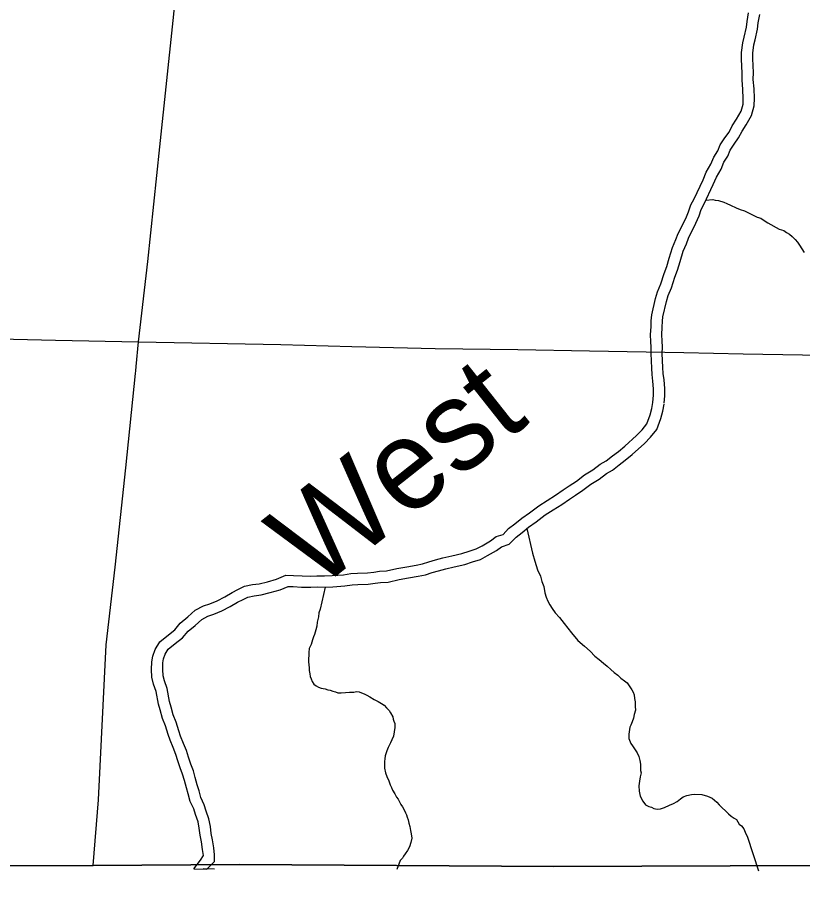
# Model space of a CAD drawing. Extents: x 2010165 to 2382125, y 1060529 to 1407316.
# Drawn here: x 2131582 to 2135077, y 1221171 to 1225012 of the extents above; entities that cross this region are included whole.
import ezdxf

# ---------------------------------------------------------------- set-up
doc = ezdxf.new("R2010")
doc.units = 0
for name, color, linetype in [('GM_X_Adjacent_County', 7, 'Continuous'), ('GM_X_City_Street', 7, 'Continuous'), ('GM_X_Corporation', 7, 'Continuous'), ('GM_X_County', 7, 'Continuous'), ('GM_X_Interstate_Route', 7, 'Continuous'), ('GM_X_Major_River', 7, 'Continuous'), ('GM_X_Major_River_Text', 7, 'Continuous'), ('GM_X_Minor_River', 7, 'Continuous'), ('GM_X_State_Route', 7, 'Continuous'), ('GM_X_Township', 7, 'Continuous')]:
    doc.layers.add(name, color=color, linetype=linetype)

msp = doc.modelspace()

# ---------------------------------------------------------------- linework, layer by layer
at = {"layer": 'GM_X_Adjacent_County'}
msp.add_lwpolyline([(2126567.4, 1221231.3), (2131919.6, 1221238.9), (2132570.2, 1221243.7), (2133969.3, 1221233.9), (2135145.8, 1221238.6), (2135226.5, 1221239.7), (2135440.8, 1221237.8), (2135741.4, 1221239.3), (2136043.5, 1221235.6), (2136342.6, 1221236.4), (2136645.5, 1221239.3), (2136937.2, 1221238.6), (2139646.1, 1221239.5), (2139604.7, 1218402.7)], dxfattribs=at)
at = {"layer": 'GM_X_City_Street'}
for points in [[(2126558, 1221231.4), (2126567.4, 1221231.3), (2131919.6, 1221238.9)], [(2132570.1, 1221243.7), (2133969.3, 1221233.9), (2135145.8, 1221238.6), (2135226.5, 1221239.7), (2135440.8, 1221237.8), (2135741.4, 1221239.3), (2136043.5, 1221235.6), (2136342.6, 1221236.4), (2136645.5, 1221239.3), (2136937.2, 1221238.6), (2139646.1, 1221239.5)]]:
    msp.add_lwpolyline(points, dxfattribs=at)
at = {"layer": 'GM_X_Corporation'}
msp.add_lwpolyline([(2135145.8, 1221238.6), (2133969.3, 1221233.9), (2132570.2, 1221243.7), (2131919.6, 1221238.9), (2126567.4, 1221231.3)], dxfattribs=at)
at = {"layer": 'GM_X_County'}
msp.add_lwpolyline([(2139604.7, 1218402.7), (2139646.1, 1221239.5), (2136937.2, 1221238.6), (2136645.5, 1221239.3), (2136342.6, 1221236.4), (2136043.5, 1221235.6), (2135741.4, 1221239.3), (2135440.8, 1221237.8), (2135226.5, 1221239.7), (2135145.8, 1221238.6), (2133969.3, 1221233.9), (2132570.2, 1221243.7), (2131919.6, 1221238.9), (2126567.4, 1221231.3)], dxfattribs=at)
at = {"layer": 'GM_X_Interstate_Route'}
for points in [[(2129183.2, 1224428.9), (2129406.8, 1224274.3), (2129545.2, 1224186), (2129820.4, 1224036.4), (2130010.5, 1223946.5), (2130302.5, 1223828.1), (2130555.7, 1223745.8), (2130707.1, 1223706.7), (2130861.1, 1223671.3), (2131070.1, 1223632.6), (2131226.9, 1223608.1), (2131383.5, 1223594.5), (2131565, 1223580), (2131751.7, 1223575), (2132122, 1223568.4)], [(2132122, 1223568.4), (2132754.5, 1223556.1), (2133070.4, 1223547.3), (2133441.3, 1223538.9), (2133809.4, 1223534), (2134128.1, 1223528.8), (2134548.5, 1223520.7), (2134812.2, 1223515.2), (2135075.9, 1223509.7), (2135241.7, 1223508.5), (2135762.8, 1223496), (2136026.5, 1223486.9), (2136287.6, 1223474.1), (2136551.4, 1223454), (2137128.7, 1223392.3), (2137651.1, 1223312), (2138066.5, 1223227.3), (2138270.1, 1223181.3), (2138476.5, 1223131.7), (2138680.1, 1223074.8), (2138977.2, 1222989.7), (2139610, 1222769.1), (2139632.9, 1222759.9)]]:
    msp.add_lwpolyline(points, dxfattribs=at)
at = {"layer": 'GM_X_Major_River'}
for p, q in [((2132367, 1221223.4), (2132424.7, 1221222.9)), ((2132459.4, 1221223.2), (2132409.4, 1221223.4))]:
    msp.add_line(p, q, dxfattribs=at)
for points in [[(2134410.4, 1223298.9), (2134413, 1223331), (2134413.4, 1223359.1), (2134410, 1223393.2), (2134406.5, 1223423.4), (2134405, 1223451.5), (2134402.1, 1223515.7), (2134402.5, 1223543.8), (2134401, 1223569.9), (2134399.5, 1223600), (2134402.1, 1223636.1), (2134402.5, 1223662.2), (2134404.9, 1223688.2), (2134422.2, 1223760.2), (2134430.7, 1223790.1), (2134445.3, 1223826), (2134460.1, 1223871.9), (2134472.6, 1223903.8), (2134483.3, 1223939.8), (2134498.1, 1223987.7), (2134512.7, 1224023.6), (2134523.2, 1224049.5), (2134556.3, 1224117.2), (2134568.9, 1224147.1), (2134579.4, 1224177.1), (2134593.9, 1224204.9), (2134633.3, 1224288.6), (2134647.9, 1224322.4), (2134668.5, 1224358.2), (2134681.1, 1224390.1), (2134699.6, 1224417.9), (2134710, 1224443.8), (2134730.6, 1224475.6), (2134749, 1224501.4), (2134763.5, 1224529.3), (2134782, 1224559.1), (2134802.7, 1224594.9), (2134811.2, 1224624.8), (2134811.6, 1224650.9), (2134810.3, 1224691.1), (2134807, 1224733.2), (2134807.5, 1224765.3), (2134806, 1224793.4), (2134804.6, 1224827.6), (2134805, 1224855.7), (2134809.8, 1224897.7), (2134816.2, 1224923.7), (2134827, 1224967.7), (2134829.4, 1224993.7), (2134836, 1225031.7)], [(2134460.3, 1223294.9), (2134463, 1223328.6), (2134463.5, 1223361.1), (2134459.7, 1223398.6), (2134456.4, 1223427.6), (2134454.9, 1223454), (2134452.1, 1223516.4), (2134452.6, 1223544.9), (2134450.9, 1223572.6), (2134449.6, 1223599.5), (2134452.1, 1223633.9), (2134452.5, 1223659.4), (2134454.4, 1223680), (2134470.6, 1223747.5), (2134478.1, 1223773.8), (2134492.3, 1223808.9), (2134507.2, 1223855.1), (2134520, 1223887.6), (2134531.2, 1223925.3), (2134545.2, 1223970.8), (2134559.1, 1224004.8), (2134568.9, 1224029.1), (2134601.9, 1224096.5), (2134615.6, 1224129.1), (2134625.4, 1224157.1), (2134638.7, 1224182.7), (2134678.9, 1224268), (2134692.7, 1224300), (2134713.7, 1224336.5), (2134725.7, 1224366.8), (2134744.1, 1224394.5), (2134754.6, 1224420.7), (2134771.9, 1224447.5), (2134791.8, 1224475.2), (2134807, 1224504.5), (2134825, 1224533.4), (2134849.1, 1224575.2), (2134861.1, 1224617.5), (2134861.7, 1224651.3), (2134860.3, 1224693.8), (2134857, 1224734.8), (2134857.6, 1224766.3), (2134856, 1224795.8), (2134854.6, 1224828.2), (2134855, 1224852.5), (2134859.1, 1224888.9), (2134864.8, 1224911.8), (2134876.4, 1224959.4), (2134879, 1224987.1), (2134885.4, 1225023.9)], [(2132367, 1221223.4), (2132398, 1221262.1), (2132410, 1221283.9), (2132406.4, 1221310), (2132401, 1221344.2), (2132395.5, 1221374.4), (2132392, 1221404.5), (2132386.4, 1221432.7), (2132375, 1221465), (2132367.4, 1221491.2), (2132351.9, 1221523.6), (2132342.5, 1221557.8), (2132334.9, 1221584), (2132325.4, 1221616.2), (2132317.9, 1221644.5), (2132306.3, 1221672.7), (2132296.9, 1221705), (2132287.3, 1221733.2), (2132275.8, 1221763.5), (2132262.3, 1221795.8), (2132252.8, 1221822.1), (2132241.4, 1221860.3), (2132227.9, 1221892.7), (2132218.5, 1221930.9), (2132211, 1221957.1), (2132199.9, 1222013.5), (2132188.4, 1222045.8), (2132180.9, 1222076), (2132179.5, 1222110.1), (2132180.1, 1222144.2), (2132184.5, 1222170.2), (2132195, 1222200.2), (2132215.6, 1222233.9), (2132254.2, 1222265.4), (2132282.6, 1222287.1), (2132307.1, 1222316.8), (2132341.6, 1222344.3), (2132374.2, 1222373.9), (2132410.6, 1222393.4), (2132438.8, 1222403), (2132471, 1222416.5), (2132505.4, 1222434), (2132537.7, 1222453.6), (2132564, 1222467.2), (2132592.3, 1222480.8), (2132628.4, 1222488.3), (2132658.5, 1222491.8), (2132694.7, 1222501.3), (2132735, 1222512.7), (2132777.3, 1222530.1), (2132811.4, 1222529.5), (2132849.4, 1222526.9), (2132887.4, 1222526.3), (2132915.5, 1222527.9), (2132949.5, 1222527.4), (2132983.6, 1222528.8), (2133033.7, 1222532.1), (2133065.9, 1222537.6), (2133095.9, 1222539.1), (2133140, 1222540.4), (2133168.1, 1222544), (2133194.2, 1222547.6), (2133224.3, 1222549.1), (2133270.5, 1222560.4), (2133314.7, 1222567.8), (2133356.9, 1222575.1), (2133385, 1222580.7), (2133413.2, 1222590.3), (2133443.4, 1222597.8), (2133475.6, 1222607.4), (2133515.8, 1222616.8), (2133560, 1222626.1), (2133592.2, 1222637.6), (2133624.4, 1222647.2), (2133650.7, 1222660.8), (2133687.1, 1222682.3), (2133713.5, 1222701.9), (2133743.7, 1222711.5), (2133768.2, 1222737.2), (2133796.5, 1222758.8), (2133827, 1222784.4), (2133861.5, 1222807.9), (2133902, 1222839.4), (2133940.5, 1222862.9), (2133976.9, 1222886.4), (2134011.4, 1222909.9), (2134037.7, 1222927.6), (2134070.1, 1222949.1), (2134106.6, 1222976.6), (2134143, 1222998.1), (2134175.5, 1223023.7), (2134201.8, 1223039.3), (2134230.2, 1223061), (2134256.6, 1223080.6), (2134285, 1223104.3), (2134337.9, 1223151.6), (2134362.3, 1223177.3), (2134382.8, 1223203), (2134397.5, 1223242.9), (2134405.9, 1223270.9), (2134410.4, 1223298.9)], [(2132424.7, 1221222.9), (2132459.6, 1221257.3), (2132460.1, 1221286.9), (2132455.9, 1221317.3), (2132450.3, 1221352.6), (2132445, 1221381.8), (2132441.4, 1221412.2), (2132434.8, 1221446), (2132422.6, 1221480.3), (2132414.3, 1221509.1), (2132399, 1221541.1), (2132390.6, 1221571.4), (2132382.9, 1221598), (2132373.6, 1221629.8), (2132365.4, 1221660.4), (2132353.6, 1221689.3), (2132344.6, 1221720), (2132334.4, 1221750.1), (2132322.3, 1221782), (2132309, 1221814), (2132300.3, 1221837.8), (2132288.6, 1221877.1), (2132275.6, 1221908.3), (2132266.9, 1221943.8), (2132259.6, 1221968.9), (2132248.3, 1222026.8), (2132236.4, 1222060.2), (2132230.7, 1222083.1), (2132229.5, 1222110.7), (2132230, 1222139.6), (2132233.1, 1222157.6), (2132240.5, 1222178.6), (2132253.9, 1222200.6), (2132285.2, 1222226.1), (2132317.5, 1222250.8), (2132342.4, 1222280.9), (2132374.1, 1222306.2), (2132403.3, 1222332.7), (2132430.6, 1222347.3), (2132456.5, 1222356.2), (2132492.1, 1222371.1), (2132529.7, 1222390.3), (2132562.2, 1222409.9), (2132586.4, 1222422.5), (2132608.4, 1222433.1), (2132636.4, 1222438.8), (2132667.8, 1222442.5), (2132707.9, 1222453), (2132751.4, 1222465.3), (2132786.8, 1222479.9), (2132809.3, 1222479.5), (2132847.3, 1222476.9), (2132888.4, 1222476.3), (2132916.5, 1222477.8), (2132950.2, 1222477.3), (2132986.3, 1222478.9), (2133039.6, 1222482.3), (2133071.4, 1222487.8), (2133097.9, 1222489.1), (2133143.9, 1222490.5), (2133174.7, 1222494.4), (2133198.9, 1222497.7), (2133231.6, 1222499.4), (2133280.6, 1222511.4), (2133323.1, 1222518.4), (2133366, 1222525.9), (2133398, 1222532.3), (2133427.4, 1222542.3), (2133456.6, 1222549.6), (2133488.4, 1222559), (2133526.7, 1222567.9), (2133573.7, 1222577.8), (2133607.8, 1222590.1), (2133643.2, 1222600.6), (2133675, 1222617), (2133714.9, 1222640.6), (2133736.6, 1222656.8), (2133771, 1222667.7), (2133801.6, 1222699.8), (2133827.8, 1222719.7), (2133857.3, 1222744.5), (2133890.9, 1222767.5), (2133930.5, 1222798.2), (2133967.1, 1222820.5), (2134004.6, 1222844.7), (2134039.4, 1222868.5), (2134065.5, 1222886), (2134099, 1222908.3), (2134134.5, 1222935), (2134171.4, 1222956.8), (2134203.9, 1222982.4), (2134229.8, 1222997.8), (2134260.3, 1223021), (2134287.5, 1223041.3), (2134317.7, 1223066.4), (2134372.7, 1223115.6), (2134400.1, 1223144.4), (2134427, 1223178.2), (2134444.9, 1223227), (2134454.8, 1223259.6), (2134459.8, 1223291)]]:
    msp.add_lwpolyline(points, dxfattribs=at)
at = {"layer": 'GM_X_Minor_River'}
for points in [[(2134646.3, 1224198.8), (2134677.3, 1224200.8), (2134687.4, 1224198.9), (2134701.4, 1224197.1), (2134725.6, 1224189.4), (2134739.7, 1224183.6), (2134755.9, 1224175.8), (2134780.1, 1224164.1), (2134798.3, 1224156.4), (2134818.4, 1224150.7), (2134838.6, 1224140.9), (2134856.8, 1224131.1), (2134874.9, 1224123.4), (2134891.1, 1224117.6), (2134905.2, 1224107.8), (2134921.4, 1224098), (2134972, 1224068.6), (2134992.1, 1224062.9), (2135004.3, 1224055), (2135018.4, 1224047.2), (2135030.6, 1224037.4), (2135042.8, 1224023.5), (2135053, 1224011.6), (2135063.2, 1223997.7), (2135073.5, 1223981.8), (2135083.8, 1223965.9)], [(2133850, 1222738.3), (2133874, 1222627.8), (2133884.5, 1222591.9), (2133897.1, 1222553.9), (2133909.5, 1222526), (2133915.9, 1222502), (2133924.3, 1222480.1), (2133928.7, 1222452), (2133935, 1222432.1), (2133943.3, 1222414.1), (2133951.5, 1222398.2), (2133961.8, 1222382.3), (2133976.1, 1222362.4), (2133994.4, 1222342.6), (2134014.9, 1222314.8), (2134047.6, 1222273.2), (2134076.1, 1222239.5), (2134106.6, 1222213.8), (2134131, 1222192.1), (2134151.3, 1222170.3), (2134171.6, 1222154.6), (2134189.9, 1222138.8), (2134206.1, 1222125), (2134222.4, 1222111.1), (2134238.6, 1222097.3), (2134254.8, 1222085.5), (2134267.1, 1222071.7), (2134283.3, 1222059.9), (2134295.4, 1222052), (2134307.7, 1222034.1), (2134315.9, 1222020.2), (2134322.1, 1222010.3), (2134326.3, 1221998.3), (2134328.5, 1221982.3), (2134330.8, 1221966.2), (2134331, 1221946.2), (2134333.3, 1221930.1), (2134327.6, 1221910), (2134323.8, 1221893.9), (2134318, 1221877.8), (2134312.2, 1221863.6), (2134308.3, 1221853.5), (2134302.8, 1221823.3), (2134303, 1221803.3), (2134311.4, 1221781.3), (2134319.5, 1221771.4), (2134331.8, 1221753.5), (2134340.1, 1221739.6), (2134348.3, 1221723.7), (2134352.6, 1221705.7), (2134354.8, 1221689.7), (2134355, 1221675.6), (2134355.2, 1221661.6), (2134357.4, 1221651.6), (2134353.6, 1221633.4), (2134349.9, 1221613.3), (2134348.2, 1221593.2), (2134348.5, 1221569.2), (2134352.9, 1221547.1), (2134365.2, 1221525.3), (2134377.5, 1221509.4), (2134391.6, 1221501.6), (2134403.7, 1221497.7), (2134413.8, 1221491.8), (2134429.9, 1221490.1), (2134443.9, 1221490.3), (2134461.9, 1221496.6), (2134483.8, 1221506.9), (2134501.7, 1221515.2), (2134517.6, 1221523.5), (2134533.5, 1221535.7), (2134545.4, 1221543.9), (2134561.4, 1221550.2), (2134581.4, 1221554.5), (2134595.4, 1221556.7), (2134627.5, 1221555.2), (2134653.7, 1221547.5), (2134673.8, 1221537.8), (2134684, 1221529.9), (2134694.2, 1221520), (2134704.4, 1221508.1), (2134747, 1221468.6), (2134759.2, 1221458.8), (2134771.4, 1221448.9), (2134781.5, 1221443), (2134793.8, 1221423.1), (2134804, 1221415.3), (2134814.2, 1221401.4), (2134820.4, 1221387.4), (2134830.8, 1221365.5), (2134880.2, 1221214.6)], [(2132951.3, 1222477.4), (2132929.1, 1222379.3), (2132923.3, 1222363.1), (2132921.6, 1222345.1), (2132915.9, 1222320.9), (2132914.2, 1222302.8), (2132910.4, 1222286.7), (2132904.7, 1222266.5), (2132900.8, 1222256.4), (2132895, 1222242.3), (2132889.3, 1222222.2), (2132881.5, 1222204), (2132879.8, 1222185.9), (2132878.4, 1222145.8), (2132878.6, 1222129.7), (2132880.8, 1222119.7), (2132881, 1222105.7), (2132883.2, 1222091.6), (2132885.3, 1222079.6), (2132889.5, 1222069.7), (2132893.7, 1222057.7), (2132901.9, 1222045.8), (2132912, 1222037.9), (2132922.1, 1222032), (2132934.2, 1222028.2), (2132952.3, 1222024.4), (2132964.4, 1222020.6), (2132974.5, 1222018.7), (2132986.5, 1222014.9), (2132998.6, 1222011.1), (2133008.7, 1222007.2), (2133022.7, 1222007.4), (2133042.8, 1222007.7), (2133060.8, 1222009.9), (2133078.9, 1222010.2), (2133090.9, 1222012.4), (2133102.9, 1222010.6), (2133113, 1222006.7), (2133125.1, 1222002.8), (2133137.2, 1221997), (2133151.3, 1221989.2), (2133169.6, 1221977.4), (2133187.8, 1221967.6), (2133201.9, 1221959.8), (2133214.1, 1221952), (2133224.2, 1221940.1), (2133236.4, 1221928.2), (2133242.6, 1221918.3), (2133252.9, 1221900.4), (2133255, 1221890.4), (2133257.2, 1221880.4), (2133261.4, 1221870.4), (2133261.6, 1221852.3), (2133256.2, 1221814.1), (2133248.4, 1221798), (2133242.6, 1221783.8), (2133232.8, 1221763.6), (2133227, 1221749.5), (2133223.2, 1221739.4), (2133219.3, 1221727.3), (2133217.5, 1221713.2), (2133215.7, 1221701.2), (2133215.9, 1221689.1), (2133216.1, 1221671.1), (2133220.4, 1221651.1), (2133226.7, 1221635.1), (2133235, 1221615.1), (2133241.3, 1221597.2), (2133247.4, 1221585.2), (2133251.6, 1221573.2), (2133261.9, 1221557.3), (2133270.1, 1221543.4), (2133276.3, 1221533.5), (2133282.5, 1221521.5), (2133288.7, 1221509.6), (2133296.8, 1221499.7), (2133303, 1221485.7), (2133309.2, 1221473.8), (2133313.4, 1221463.8), (2133317.5, 1221453.8), (2133321.7, 1221441.8), (2133323.9, 1221427.8), (2133328.2, 1221411.8), (2133332.4, 1221393.8), (2133334.7, 1221379.8), (2133337, 1221359.8), (2133333.2, 1221341.7), (2133327.5, 1221321.5), (2133317.7, 1221305.3), (2133307.9, 1221291.1), (2133300, 1221281), (2133296.1, 1221270.9), (2133286.2, 1221260.7), (2133270.2, 1221220.3)]]:
    msp.add_lwpolyline(points, dxfattribs=at)
at = {"layer": 'GM_X_State_Route'}
for points in [[(2132108.9, 1223439.8), (2132110.8, 1223458.2), (2132122, 1223568.4), (2132162.5, 1223925.1), (2132216.3, 1224436.1), (2132276, 1224997.2), (2132331.7, 1225556.2), (2132346.7, 1225689.7)], [(2131919.6, 1221238.9), (2131943.4, 1221530.4), (2131977.4, 1222219.8), (2132017.3, 1222566.5), (2132065, 1223007.3), (2132107.6, 1223426.8), (2132108.9, 1223439.8)]]:
    msp.add_lwpolyline(points, dxfattribs=at)
at = {"layer": 'GM_X_Township'}
msp.add_lwpolyline([(2136847, 1225123.7), (2136882.5, 1223487.8), (2138178, 1223285.3), (2138918.5, 1223089.4), (2139653.2, 1222853.3), (2139651.5, 1222752.4), (2139646.1, 1221239.5), (2136937.2, 1221238.6), (2136645.5, 1221239.3), (2136342.6, 1221236.4), (2136043.5, 1221235.6), (2135741.4, 1221239.3), (2135440.8, 1221237.8), (2135226.5, 1221239.7), (2135145.8, 1221238.6), (2133969.3, 1221233.9), (2132570.2, 1221243.7), (2131919.6, 1221238.9), (2126567.4, 1221231.3)], dxfattribs=at)

# ---------------------------------------------------------------- texts
at = {"layer": 'GM_X_Major_River_Text'}
msp.add_text('West', height=400.23, rotation=38.3806, dxfattribs=at).set_placement((2132911.1, 1222455))

doc.saveas('drawing.dxf')
